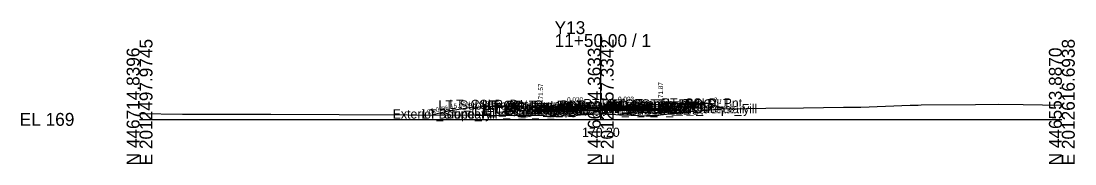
# Model space of a CAD drawing. Extents: x -26 to 1403, y -10 to 4517.
# Drawn here: x -25.7 to 202.8, y 2990.3 to 3021.4 of the extents above; entities that cross this region are included whole.
import ezdxf

# ---------------------------------------------------------------- set-up
doc = ezdxf.new("R2010")
doc.units = 0
for name, color, linetype in [('Default', 7, 'Continuous'), ('Exist Cross Section Cell', 7, 'Continuous'), ('Exist XS Center Line Elevation Label', 7, 'Continuous'), ('Exist XS Ground Line', 7, 'Continuous'), ('Prop CMT Conc Surface', 7, 'Continuous'), ('Prop CMT Concrete Structures', 7, 'Continuous'), ('Prop CMT Pvmt Course 1', 7, 'Continuous'), ('Prop CMT Pvmt Course 1 CG', 7, 'Continuous'), ('Prop CMT Pvmt Course 2', 7, 'Continuous'), ('Prop CMT Pvmt Course 3', 7, 'Continuous'), ('Prop CMT Pvmt Surface', 7, 'Continuous'), ('Prop CMT Slope Grass', 7, 'Continuous'), ('Prop CMT Subgrade Earthwork', 7, 'Continuous'), ('Prop XS Earthwork Shape', 7, 'Continuous'), ('Prop XS Hydro Elevations', 7, 'Continuous'), ('Prop XS SE Text', 7, 'Continuous'), ('Prop XS Side Slope Text', 7, 'Continuous'), ('Scratch_Level_0', 7, 'Continuous')]:
    doc.layers.add(name, color=color, linetype=linetype)

msp = doc.modelspace()

# ---------------------------------------------------------------- linework, layer by layer
at = {"layer": 'Exist Cross Section Cell'}
for p, q in [((100, 3000), (100, 3018.54)), ((0, 3000), (100, 3000)), ((100, 3000), (200, 3000))]:
    msp.add_line(p, q, dxfattribs=at)
at = {"layer": 'Exist XS Ground Line'}
msp.add_lwpolyline([(0, 3001.28), (9.3, 3001.1), (28.5, 3001.14), (87.81, 3000.85), (89.22, 3000.62), (99.49, 3001.22), (100, 3001.2), (111.54, 3000.71), (113, 3000.98), (120.12, 3001.75), (126.22, 3002.32), (131.58, 3002.38), (135.79, 3002.41), (144.01, 3002.54), (152.64, 3002.65), (156.44, 3002.67), (167.13, 3003.07), (168.87, 3003.12), (169.49, 3003.14), (181.3, 3003.27), (186.33, 3003.28), (191.59, 3003.25), (200, 3003.12)], dxfattribs=at)
at = {"layer": 'Prop CMT Conc Surface'}
for p, q in [((67, 3001.82), (63.58, 3000.97)), ((72, 3002.57), (67, 3001.82)), ((77, 3002.77), (72, 3002.57)), ((87, 3002.57), (77, 3002.77))]:
    msp.add_line(p, q, dxfattribs=at)
for points in [[(111, 3002.94), (113, 3002.87)], [(113, 3002.87), (113, 3003.37), (113.5, 3003.37)], [(89, 3002.69), (87, 3002.57)]]:
    msp.add_lwpolyline(points, dxfattribs=at)
at = {"layer": 'Prop CMT Concrete Structures'}
for points in [[(111, 3002.94), (113, 3002.87), (113, 3003.37), (113.5, 3003.37)], [(113.5, 3003.37), (113.5, 3002.36), (111, 3002.36)], [(111, 3002.36), (111, 3002.94)], [(86.5, 3002.58), (86.5, 3002.06), (89, 3002.11)], [(89, 3002.11), (89, 3002.69)]]:
    msp.add_lwpolyline(points, dxfattribs=at)
at = {"layer": 'Prop CMT Pvmt Course 1'}
for points in [[(100, 3002.91), (111, 3002.94)], [(111, 3002.94), (111, 3002.69)], [(100, 3002.91), (89, 3002.69)], [(89, 3002.69), (89, 3002.44)], [(89, 3002.44), (100, 3002.66)], [(100, 3002.66), (100, 3002.91)], [(100, 3002.66), (100, 3002.91)], [(111, 3002.69), (100, 3002.66)]]:
    msp.add_lwpolyline(points, dxfattribs=at)
msp.add_lwpolyline([(100, 3002.66), (100, 3002.79), (100, 3002.79), (100, 3002.66)], close=True, dxfattribs=at)
msp.add_lwpolyline([(100, 3002.66), (100, 3002.79), (100, 3002.79), (100, 3002.66)], close=True, dxfattribs=at)
at = {"layer": 'Prop CMT Pvmt Course 1 CG'}
for points in [[(89, 3002.11), (86, 3002.05), (85.66, 3001.71)], [(85.66, 3001.71), (89, 3001.78)], [(89, 3001.78), (89, 3002.11)], [(111, 3002.36), (114, 3002.37), (114.33, 3002.03)], [(111, 3002.02), (111, 3002.36)], [(114.33, 3002.03), (111, 3002.02)]]:
    msp.add_lwpolyline(points, dxfattribs=at)
at = {"layer": 'Prop CMT Pvmt Course 2'}
for points in [[(100, 3002.66), (89, 3002.44)], [(89, 3002.44), (89, 3002.11)], [(89, 3002.11), (100, 3002.33)], [(100, 3002.66), (111, 3002.69)], [(100, 3002.33), (100, 3002.66)], [(100, 3002.33), (100, 3002.66)], [(111, 3002.36), (100, 3002.33)], [(111, 3002.69), (111, 3002.36)]]:
    msp.add_lwpolyline(points, dxfattribs=at)
at = {"layer": 'Prop CMT Pvmt Course 3'}
for points in [[(100, 3002.33), (89, 3002.11)], [(89, 3002.11), (89, 3001.78)], [(89, 3001.78), (100, 3002)], [(100, 3002.33), (111, 3002.36)], [(100, 3002), (100, 3002.33)], [(100, 3002), (100, 3002.33)], [(111, 3002.02), (100, 3002)], [(111, 3002.36), (111, 3002.02)]]:
    msp.add_lwpolyline(points, dxfattribs=at)
at = {"layer": 'Prop CMT Pvmt Surface'}
for points in [[(100, 3002.91), (111, 3002.94)], [(100, 3002.91), (89, 3002.69)]]:
    msp.add_lwpolyline(points, dxfattribs=at)
at = {"layer": 'Prop CMT Slope Grass'}
msp.add_lwpolyline([(113.5, 3003.37), (123, 3003.56), (126.69, 3002.33)], dxfattribs=at)
at = {"layer": 'Prop CMT Subgrade Earthwork'}
for points in [[(111, 3002.02), (114.33, 3002.03), (115.71, 3003.41)], [(89, 3001.78), (85.66, 3001.71), (84.75, 3002.62)], [(100, 3002), (89, 3001.78)], [(100, 3002), (111, 3002.02)]]:
    msp.add_lwpolyline(points, dxfattribs=at)
at = {"layer": 'Prop XS Earthwork Shape'}
msp.add_lwpolyline([(100, 3002), (89, 3001.78), (85.66, 3001.71), (84.75, 3002.62), (77, 3002.77), (72, 3002.57), (67, 3001.82), (63.58, 3000.97), (87.81, 3000.85), (89.22, 3000.62), (99.49, 3001.22), (100, 3001.2), (111.54, 3000.71), (113, 3000.98), (120.12, 3001.75), (126.22, 3002.32), (126.69, 3002.33), (123, 3003.56), (115.71, 3003.41), (114.33, 3002.03), (111, 3002.02)], close=True, dxfattribs=at)

# ---------------------------------------------------------------- texts
at = {"layer": 'Default'}
msp.add_text('-', height=0.0001, dxfattribs=at).set_placement((0, 3000))
at = {"layer": 'Exist Cross Section Cell'}
for s, p in [('Y13', (90, 3018.54)), ('11+50.00 / 1', (90, 3015.74)), ('EL 169', (-26, 2998.6))]:
    msp.add_text(s, height=2.8, dxfattribs=at).set_placement(p)
for s, p in [('E 2012497.9745', (2.8, 2990)), ('E 2012557.3342', (102.8, 2990)), ('E 2012616.6938', (202.8, 2990)), ('N 446714.8396', (0, 2990)), ('N 446634.3633', (100, 2990)), ('N 446553.8870', (200, 2990))]:
    msp.add_text(s, height=2.8, rotation=90, dxfattribs=at).set_placement(p)
at = {"layer": 'Exist XS Center Line Elevation Label'}
msp.add_text('170.20', height=2, dxfattribs=at).set_placement((95.95, 2996.2))
at = {"layer": 'Prop XS Hydro Elevations'}
for s, p in [('171.57', (87.5, 3003.57)), ('171.87', (113.5, 3003.87))]:
    msp.add_text(s, height=1, rotation=90, dxfattribs=at).set_placement(p)
at = {"layer": 'Prop XS SE Text'}
for s, rotation, p in [('0.020', 1.1458, (92.73, 3003.77)), ('0.003', 0.1432, (103.77, 3003.92))]:
    msp.add_text(s, height=1, rotation=rotation, dxfattribs=at).set_placement(p)
at = {"layer": 'Prop XS Side Slope Text'}
for s, rotation, p in [('25.00%', 14.0362, (62.49, 3001.06)), ('15.00%', 8.5308, (67.43, 3002.25)), ('4.00%', 2.2906, (72.56, 3002.91)), ('3:1', 341.5668, (124.33, 3003.9))]:
    msp.add_text(s, height=1, rotation=rotation, dxfattribs=at).set_placement(p)
at = {"layer": 'Scratch_Level_0'}
for s, p in [('LT_Sub_Trench_Out_DLT', (64.82, 3002.12)), ('LT_CSLP_Pnt', (67.17, 3002.26)), ('LT_CG1_Shelf_Out', (72.55, 3001.05)), ('LT_CG_Top_Face', (74.26, 3002.07)), ('LT_CG_Top_BOC', (74.78, 3002.07)), ('LT_CG_Bot_BOC', (74.81, 3001.06)), ('LT_CG_Top_Gut', (75.24, 3001.57)), ('LT_CG_Bot_IE', (78.91, 3001.11)), ('LT_PV2_OEOT', (79.17, 3001.44)), ('LT_PV3_OEOT', (79.17, 3001.11)), ('LT_PV1_OEOT', (79.74, 3001.69)), ('RT_Sub_OEEOP', (89.17, 3001)), ('LT_Sub_OEEOP', (89.21, 3001)), ('RT_PV2_OEEOP', (89.26, 3001.66)), ('RT_PV3_OEEOP', (89.26, 3001.33)), ('LT_PV2_OEEOP', (89.31, 3001.66)), ('LT_PV3_OEEOP', (89.31, 3001.33)), ('RT_PV1_OEEOP', (89.83, 3001.79)), ('LT_PV1_OEEOP', (89.87, 3001.79)), ('RT_PV2_IEEOP', (89.91, 3001.66)), ('LT_PV2_IEEOP', (89.95, 3001.66)), ('RT_PV1_IEEOP', (90.47, 3001.79)), ('LT_PV1_IEEOP', (90.52, 3001.79)), ('PV2_PGL', (93.91, 3001.66)), ('PV1_PGL', (94.47, 3001.91)), ('RT_Sub_Trench_Out_DLT', (96.23, 3002.41)), ('RT_CG_Top_Face', (100.21, 3002.37)), ('RT_CG1_Shelf_Out', (100.5, 3001.37)), ('RT_CG_Bot_IE', (100.87, 3001.36)), ('RT_Sub_OEOT', (101.03, 3001.02)), ('RT_PV2_OEOT', (101.13, 3001.69)), ('RT_PV3_OEOT', (101.13, 3001.36)), ('RT_CG_Top_Gut', (101.19, 3001.87)), ('RT_PV1_OEOT', (101.69, 3001.94)), ('RT_CG_Top_BOC', (101.74, 3002.37)), ('RT_CG_Bot_BOC', (101.77, 3001.36)), ('RT_Sub_OEOP', (104.4, 3001.03)), ('Exterior Boundary', (110.83, 3001.33)), ('RT_CSLP_Pnt', (113.13, 3002.56)), ('RT_Slope_Fill', (117.16, 3001.33)), ('Exterior Boundary', (54.89, 3000.18)), ('LT_Slope_Fill', (61.27, 3000.18)), ('LT_Sub_OEOP', (75.77, 3000.71)), ('LT_Sub_OEOT', (79.08, 3000.78))]:
    msp.add_text(s, height=2, dxfattribs=at).set_placement(p)

doc.saveas('drawing.dxf')
